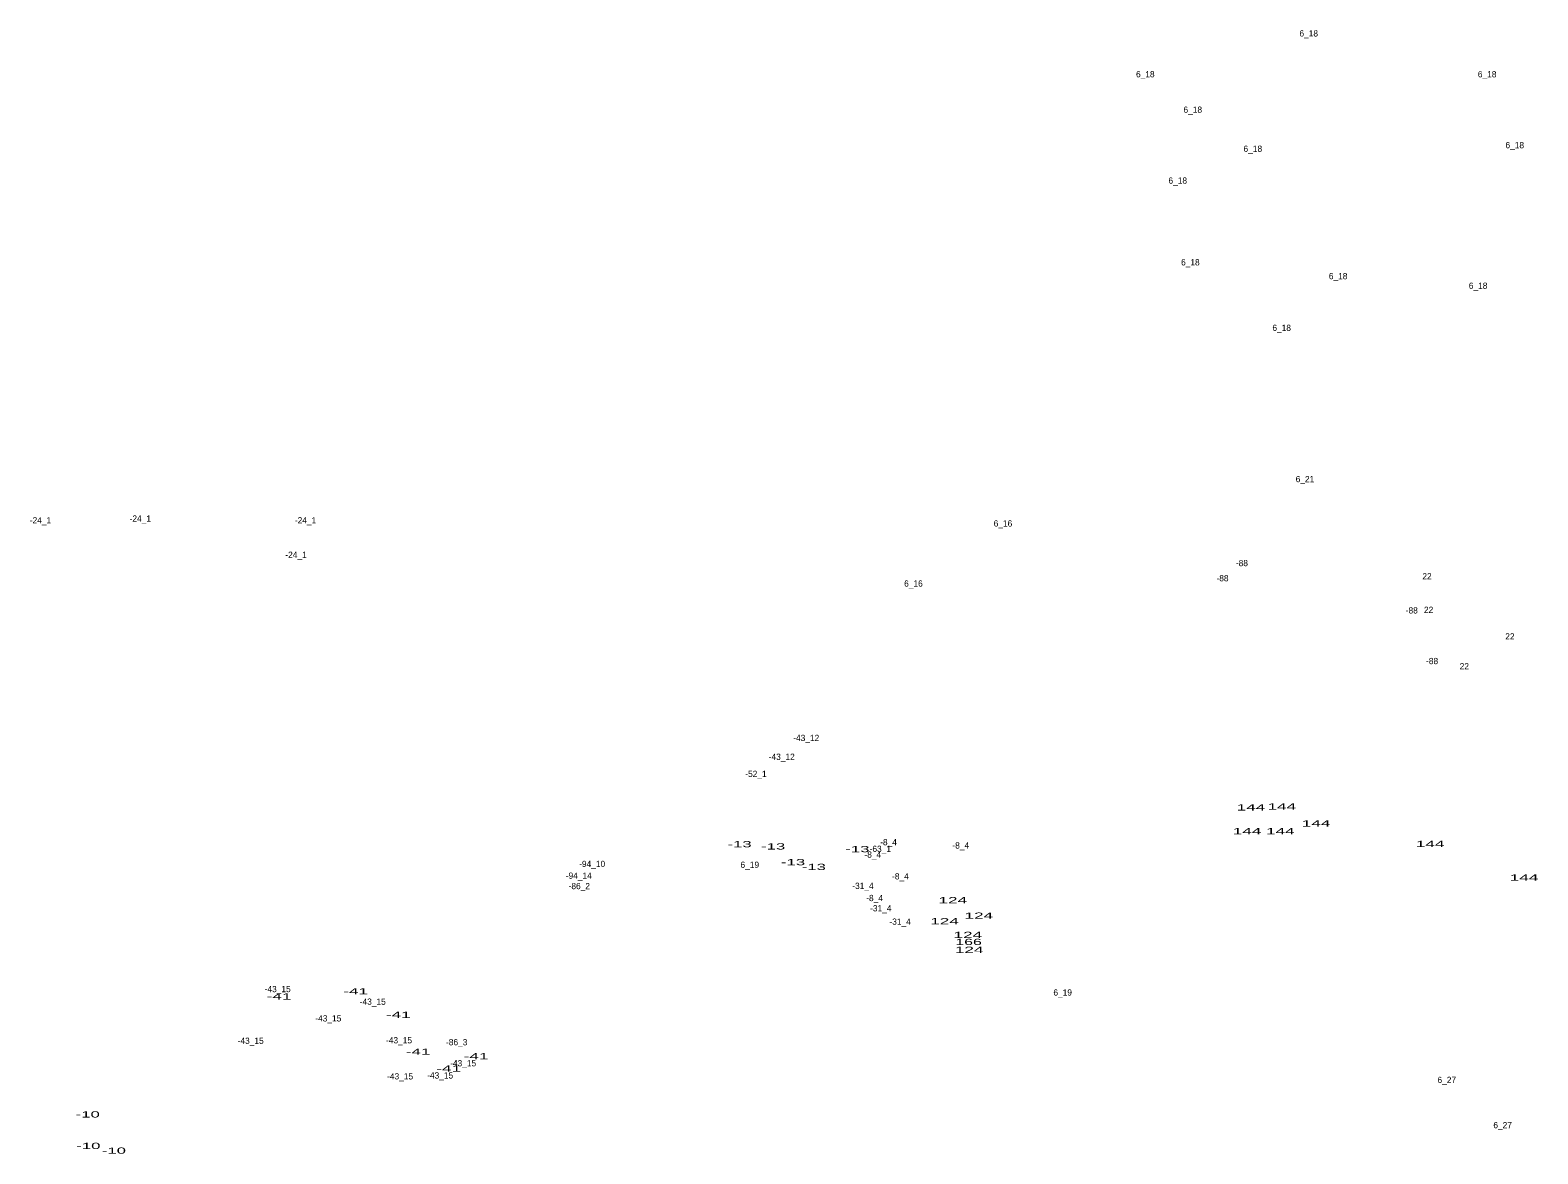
# Model space of a CAD drawing. Extents: x -659624 to -656248, y -1006345 to -1003555.
# Drawn here: x -659624 to -658659, y -1004993 to -1004274 of the extents above; entities that cross this region are included whole.
import ezdxf
from ezdxf.enums import TextEntityAlignment as Align

# ---------------------------------------------------------------- set-up
doc = ezdxf.new("R2010")
doc.units = 0
doc.header["$LTSCALE"] = 1.6
doc.layers.add('24', color=7, linetype='Continuous')

msp = doc.modelspace()

# ---------------------------------------------------------------- texts
at = {"layer": '24'}
for s, p in [('6_18', (-658805.234, -1004277.69)), ('6_18', (-658909.814, -1004303.85)), ('6_18', (-658691.044, -1004303.85)), ('6_18', (-658879.434, -1004326.54)), ('6_18', (-658673.364, -1004349.23)), ('6_18', (-658840.994, -1004351.54)), ('6_18', (-658889.054, -1004371.92)), ('6_18', (-658880.974, -1004424.23)), ('6_18', (-658786.394, -1004433.08)), ('6_18', (-658696.814, -1004439.23)), ('6_18', (-658822.534, -1004466.15)), ('6_21', (-658807.634, -1004563)), ('-24_1', (-659616.9, -1004589.39)), ('-24_1', (-659553, -1004588.25)), ('-24_1', (-659447.26, -1004589.39)), ('6_16', (-659000.92, -1004591.38)), ('-24_1', (-659453.34, -1004611.46)), ('-88', (-658847.975, -1004616.75)), ('-88', (-658860.395, -1004626.46)), ('22', (-658729.537, -1004625.25)), ('6_16', (-659058.21, -1004629.85)), ('-88', (-658739.275, -1004647.04)), ('22', (-658728.487, -1004646.65)), ('22', (-658676.477, -1004663.68)), ('-88', (-658726.265, -1004679.47)), ('22', (-658705.657, -1004682.8)), ('-43_12', (-659126.82, -1004728.71)), ('-43_12', (-659142.49, -1004740.73)), ('-52_1', (-659158.996, -1004751.71)), ('-63_1', (-659079.422, -1004799.68)), ('-8_4', (-659074.138, -1004795.4)), ('-8_4', (-659027.928, -1004797.5)), ('-94_10', (-659263.82, -1004809.35)), ('6_19', (-659162.94, -1004809.88)), ('-8_4', (-659084.208, -1004803.35)), ('-94_14', (-659272.37, -1004816.86)), ('-8_4', (-659066.528, -1004817.28)), ('-86_2', (-659272.068, -1004823.52)), ('-31_4', (-659090.51, -1004823.36)), ('-8_4', (-659083.078, -1004831.17)), ('-31_4', (-659079.1, -1004837.73)), ('-31_4', (-659066.73, -1004846.29)), ('-43_15', (-659465.1, -1004889.44)), ('-43_15', (-659404.25, -1004897.51)), ('6_19', (-658962.7, -1004891.65)), ('-43_15', (-659432.69, -1004908.2)), ('-43_15', (-659482.38, -1004922.52)), ('-43_15', (-659387.44, -1004922.23)), ('-86_3', (-659350.518, -1004923.46)), ('-43_15', (-659346.39, -1004936.93)), ('-43_15', (-659386.73, -1004945.31)), ('-43_15', (-659361.1, -1004944.73)), ('6_27', (-658716.886, -1004947.62)), ('6_27', (-658681.126, -1004976.54))]:
    msp.add_text(s, height=4, dxfattribs=at).set_placement(p, align=Align.CENTER)
for s, width, p in [('144', 2.05, (-658842.199, -1004773.15)), ('144', 2.05, (-658822.429, -1004772.58)), ('144', 2.05, (-658800.549, -1004783.42)), ('144', 2.05, (-658844.679, -1004788.37)), ('144', 2.05, (-658823.379, -1004788.37)), ('-13', 2, (-659169.491, -1004796.69)), ('-13', 2, (-659148.001, -1004798.12)), ('-13', 2, (-659094.081, -1004799.83)), ('144', 2.05, (-658727.519, -1004796.55)), ('-13', 2, (-659135.251, -1004808.2)), ('-13', 2, (-659121.941, -1004811.25)), ('144', 2.05, (-658667.419, -1004818.05)), ('124', 2.05, (-659033.023, -1004832.57)), ('124', 2.05, (-659038.313, -1004846.03)), ('124', 2.05, (-659016.393, -1004842.47)), ('124', 2.05, (-659023.413, -1004854.78)), ('166', 1.9, (-659022.917, -1004859.27)), ('124', 2.05, (-659022.543, -1004864.3)), ('-41', 2.05, (-659464.206, -1004894.16)), ('-41', 2.05, (-659415.196, -1004890.89)), ('-41', 2.05, (-659387.896, -1004905.89)), ('-41', 2.05, (-659375.196, -1004929.55)), ('-41', 2.05, (-659338.106, -1004932.44)), ('-41', 2.05, (-659355.606, -1004940.31)), ('-10', 2, (-659586.647, -1004969.67)), ('-10', 2, (-659586.267, -1004989.84)), ('-10', 2, (-659569.907, -1004992.88))]:
    msp.add_text(s, height=4, dxfattribs=dict(at, width=width)).set_placement(p, align=Align.CENTER)

doc.saveas('drawing.dxf')
